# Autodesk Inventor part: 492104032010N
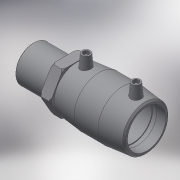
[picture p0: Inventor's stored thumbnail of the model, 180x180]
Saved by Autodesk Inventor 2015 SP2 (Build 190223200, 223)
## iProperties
Created: 2017-06
Part Number: 492104032010N
Material: Generic
Description: PLASSON Male Transition Coupler 32 x 1"
Document SubType Name: Modeling
Designer: KIM
Mass: 102.755 g
Surface Area: 364.823 cm^2
Volume: 102.755 cm^3
Density: 1 g/cm^3
Appearance: Default
Author: KIM
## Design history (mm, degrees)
derived "492104.ipt"
feature "Solid1::492104.ipt"
tag "TaggingFeature1"
body "Solid1"
other parameters: "d1" = 32, "d2" = 44, "d3" = 44, "d5" = 39.6, "d6" = 30.4, "d7" = 32, "d8" = 168 deg, "d10" = 17.6, "d11" = 5.86667, "d29" = 43, "d30" = 14, "d31" = 31.5, "d34" = 5 deg, "d41" = 4, "d42" = 14, "d43" = 0, "d48" = 3, "d49" = 0, "d57" = 22, "d58" = 33.249, "d59" = 26.5992, "d60" = 45, "d61" = 44, "d62" = 0.66498, "d65" = 1.32, "d70" = 0.1, "d72" = 12.5, "d73" = 17.6, "d75" = 0, "d_" = 32, "L_1" = 44, "D_1" = 44, "A_" = 43, "d_2" = 12, "D_" = 22, "R_" = 33.249
